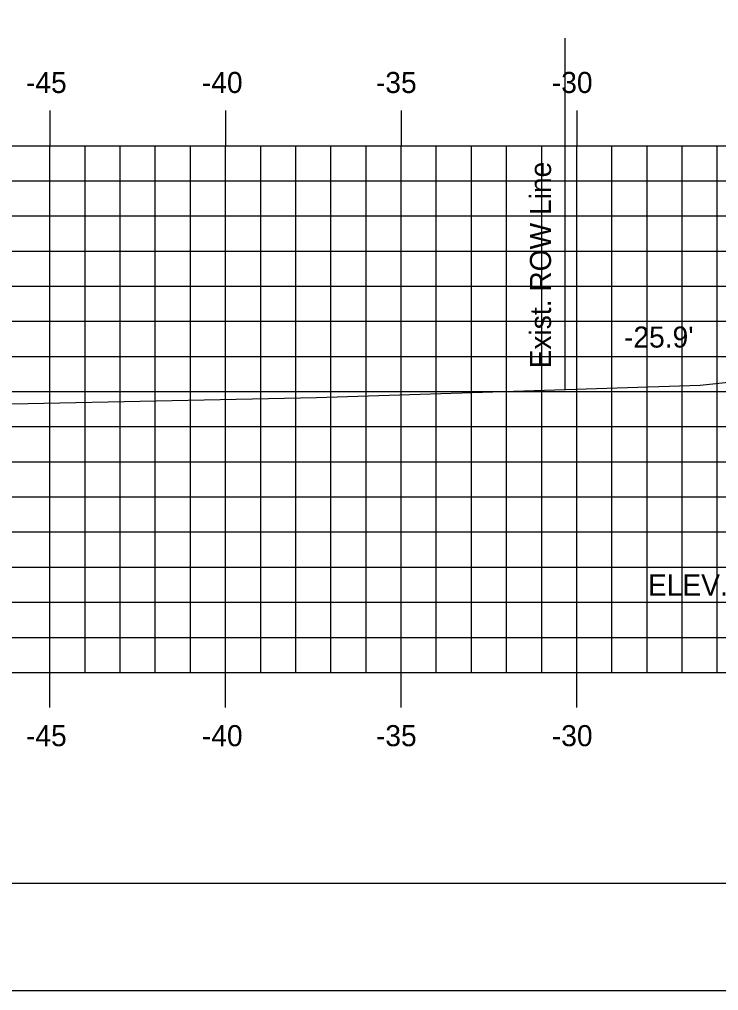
# Model space of a CAD drawing. Extents: x 854676 to 854846, y 366268 to 366378.
# Drawn here: x 854713.24 to 854733.14, y 366268.18 to 366295.83 of the extents above; entities that cross this region are included whole.
import ezdxf

# ---------------------------------------------------------------- set-up
doc = ezdxf.new("R2010")
doc.units = 0
for name, color, linetype in [('BORDER', 7, 'Continuous'), ('D_Text_Standard', 7, 'Continuous'), ('E_ROW_Line', 7, 'Continuous'), ('H_V ANNOTATION', 7, 'Continuous'), ('MAJOR', 7, 'Continuous'), ('MINOR', 7, 'Continuous'), ('PLOT BOUNDARY', 7, 'Continuous'), ('S_Roadway_Centerline', 7, 'Continuous')]:
    doc.layers.add(name, color=color, linetype=linetype)

msp = doc.modelspace()

# ---------------------------------------------------------------- linework, layer by layer
at = {"layer": 'BORDER'}
msp.add_line((854684.107, 366271.236), (854844.107, 366271.236), dxfattribs=at)
at = {"layer": 'E_ROW_Line'}
msp.add_line((854728.772, 366285.293), (854728.772, 366295.293), dxfattribs=at)
at = {"layer": 'MAJOR'}
for p, q in [((854714.106, 366293.238), (854714.106, 366292.236)), ((854719.106, 366293.238), (854719.106, 366292.236)), ((854724.106, 366293.238), (854724.106, 366292.236)), ((854729.106, 366293.238), (854729.106, 366292.236)), ((854689.106, 366292.236), (854829.106, 366292.236)), ((854689.106, 366292.236), (854829.106, 366292.236)), ((854714.106, 366277.236), (854714.106, 366292.236)), ((854719.106, 366277.236), (854719.106, 366292.236)), ((854724.106, 366277.236), (854724.106, 366292.236)), ((854729.106, 366277.236), (854729.106, 366292.236)), ((854689.106, 366287.236), (854829.106, 366287.236)), ((854689.106, 366282.236), (854829.106, 366282.236)), ((854689.106, 366277.236), (854829.106, 366277.236)), ((854689.106, 366277.236), (854829.106, 366277.236)), ((854714.106, 366276.234), (854714.106, 366277.236)), ((854719.106, 366276.234), (854719.106, 366277.236)), ((854724.106, 366276.234), (854724.106, 366277.236)), ((854729.106, 366276.234), (854729.106, 366277.236))]:
    msp.add_line(p, q, dxfattribs=at)
at = {"layer": 'MINOR'}
for p, q in [((854715.106, 366277.236), (854715.106, 366292.236)), ((854716.106, 366277.236), (854716.106, 366292.236)), ((854717.106, 366277.236), (854717.106, 366292.236)), ((854718.106, 366277.236), (854718.106, 366292.236)), ((854720.106, 366277.236), (854720.106, 366292.236)), ((854721.106, 366277.236), (854721.106, 366292.236)), ((854722.106, 366277.236), (854722.106, 366292.236)), ((854723.106, 366277.236), (854723.106, 366292.236)), ((854725.106, 366277.236), (854725.106, 366292.236)), ((854726.106, 366277.236), (854726.106, 366292.236)), ((854727.106, 366277.236), (854727.106, 366292.236)), ((854728.106, 366277.236), (854728.106, 366292.236)), ((854730.106, 366277.236), (854730.106, 366292.236)), ((854731.106, 366277.236), (854731.106, 366292.236)), ((854732.106, 366277.236), (854732.106, 366292.236)), ((854733.106, 366277.236), (854733.106, 366292.236)), ((854689.106, 366291.236), (854829.106, 366291.236)), ((854689.106, 366290.236), (854829.106, 366290.236)), ((854689.106, 366289.236), (854829.106, 366289.236)), ((854689.106, 366288.236), (854829.106, 366288.236)), ((854689.106, 366286.236), (854829.106, 366286.236)), ((854689.106, 366285.236), (854829.106, 366285.236)), ((854689.106, 366284.236), (854829.106, 366284.236)), ((854689.106, 366283.236), (854829.106, 366283.236)), ((854689.106, 366281.236), (854829.106, 366281.236)), ((854689.106, 366280.236), (854829.106, 366280.236)), ((854689.106, 366279.236), (854829.106, 366279.236)), ((854689.106, 366278.236), (854829.106, 366278.236))]:
    msp.add_line(p, q, dxfattribs=at)
at = {"layer": 'PLOT BOUNDARY'}
msp.add_lwpolyline([(854676.013, 366268.177), (854846.013, 366268.177), (854846.013, 366378.177), (854676.013, 366378.177)], close=True, dxfattribs=at)
at = {"layer": 'S_Roadway_Centerline'}
msp.add_lwpolyline([(854700.471, 366284.322), (854708.905, 366284.797), (854721.694, 366285.065), (854732.614, 366285.415), (854735.383, 366285.709), (854736.899, 366285.86), (854739.868, 366285.754), (854740.379, 366285.723), (854740.556, 366285.66), (854741.471, 366285.366), (854747.7, 366285.585), (854748.52, 366285.618), (854758.547, 366285.5), (854759.829, 366285.5), (854761.239, 366285.468), (854771.879, 366285.217)], dxfattribs=at)

# ---------------------------------------------------------------- texts
at = {"layer": 'D_Text_Standard'}
for s, p in [("-25.9'", (854730.45, 366286.487)), ('ELEV. = 267.49', (854731.13, 366279.426))]:
    msp.add_text(s, height=0.6, dxfattribs=at).set_placement(p)
at = {"layer": 'E_ROW_Line'}
msp.add_text('Exist. ROW Line', height=0.6, rotation=90, dxfattribs=at).set_placement((854728.372, 366285.893))
at = {"layer": 'H_V ANNOTATION'}
for s, p in [('-45', (854713.424, 366293.736)), ('-40', (854718.432, 366293.736)), ('-35', (854723.387, 366293.736)), ('-30', (854728.395, 366293.736)), ('-45', (854713.424, 366275.136)), ('-40', (854718.432, 366275.136)), ('-35', (854723.387, 366275.136)), ('-30', (854728.395, 366275.136))]:
    msp.add_text(s, height=0.6, dxfattribs=at).set_placement(p)

doc.saveas('drawing.dxf')
